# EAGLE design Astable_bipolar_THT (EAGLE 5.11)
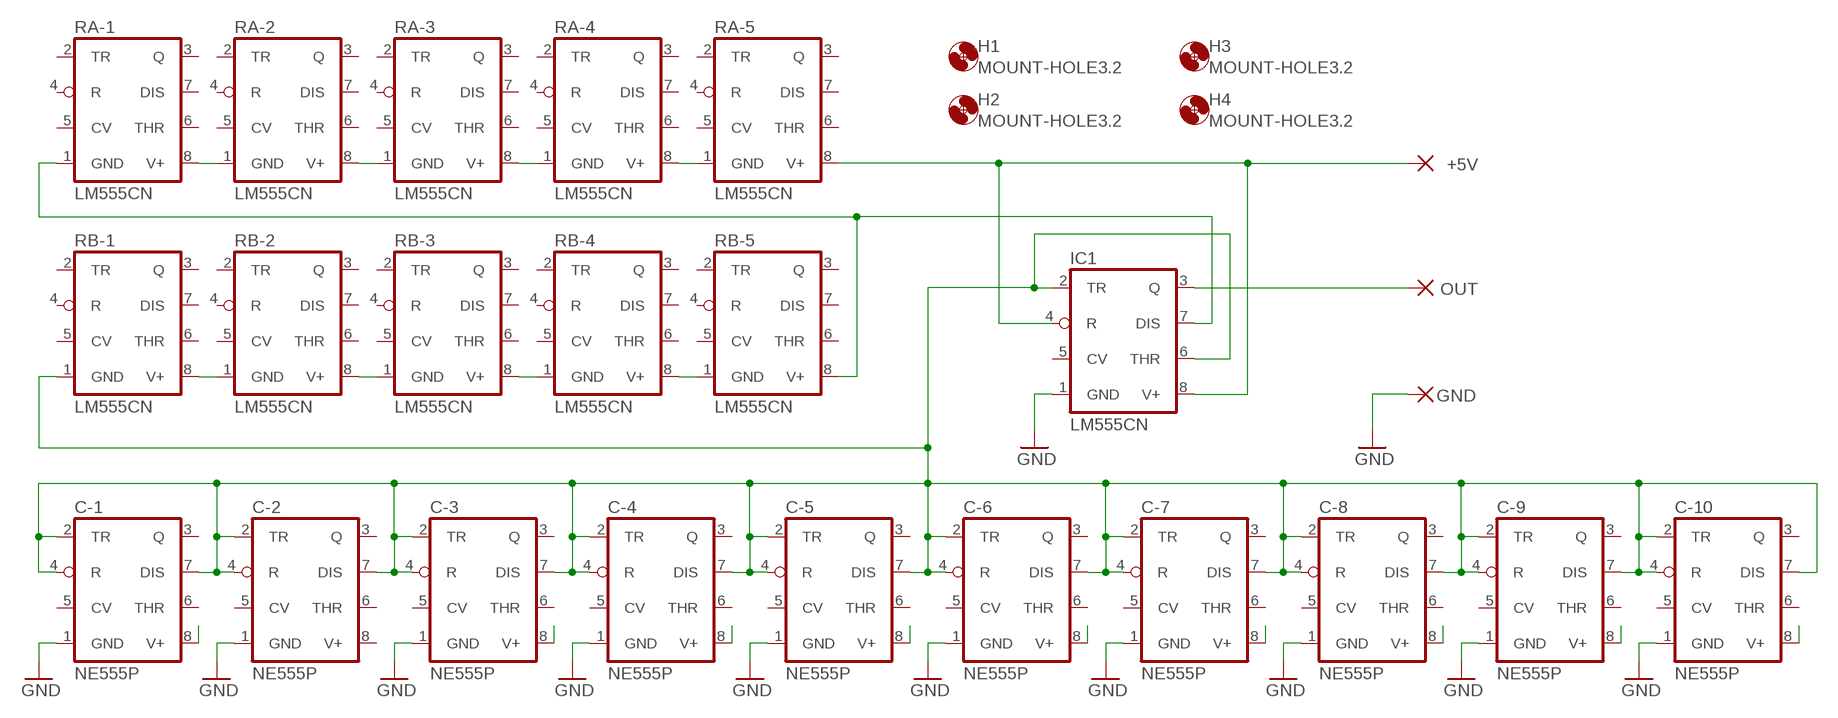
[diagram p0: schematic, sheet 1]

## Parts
+5V  3,17/1,1  [3,17/1,1]
C-1  NE555P  NE555N  [DIL08]
C-2  NE555P  NE555N  [DIL08]
C-3  NE555P  NE555N  [DIL08]
C-4  NE555P  NE555N  [DIL08]
C-5  NE555P  NE555N  [DIL08]
C-6  NE555P  NE555N  [DIL08]
C-7  NE555P  NE555N  [DIL08]
C-8  NE555P  NE555N  [DIL08]
C-9  NE555P  NE555N  [DIL08]
C-10  NE555P  NE555N  [DIL08]
GND  3,17/1,1  [3,17/1,1]
H1  MOUNT-HOLE3.2  [3,2]
H2  MOUNT-HOLE3.2  [3,2]
H3  MOUNT-HOLE3.2  [3,2]
H4  MOUNT-HOLE3.2  [3,2]
IC1  LM555CN  NE555N  [DIL08]
OUT  3,17/1,1  [3,17/1,1]
RA-1  LM555CN  NE555N  [DIL08]
RA-2  LM555CN  NE555N  [DIL08]
RA-3  LM555CN  NE555N  [DIL08]
RA-4  LM555CN  NE555N  [DIL08]
RA-5  LM555CN  NE555N  [DIL08]
RB-1  LM555CN  NE555N  [DIL08]
RB-2  LM555CN  NE555N  [DIL08]
RB-3  LM555CN  NE555N  [DIL08]
RB-4  LM555CN  NE555N  [DIL08]
RB-5  LM555CN  NE555N  [DIL08]

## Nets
GND: C-1.1(GND) C-2.1(GND) C-3.1(GND) C-4.1(GND) C-5.1(GND) C-6.1(GND) C-7.1(GND) C-8.1(GND) C-9.1(GND) C-10.1(GND) GND.1(P) IC1.1(GND)
N$1: +5V.1(P) IC1.4(R) IC1.8(V+) RA-5.8(V+)
N$2: IC1.7(DIS) RA-1.1(GND) RB-5.8(V+)
N$3: C-1.8(V+)
N$4: C-3.8(V+)
N$5: C-4.8(V+)
N$6: C-5.8(V+)
N$7: C-1.2(TR) C-1.4(R) C-1.7(DIS) C-2.2(TR) C-2.4(R) C-2.7(DIS) C-3.2(TR) C-3.4(R) C-3.7(DIS) C-4.2(TR) C-4.4(R) C-4.7(DIS) C-5.2(TR) C-5.4(R) C-5.7(DIS) C-6.2(TR) C-6.4(R) C-6.7(DIS) C-7.2(TR) C-7.4(R) C-7.7(DIS) C-8.2(TR) C-8.4(R) C-8.7(DIS) C-9.2(TR) C-9.4(R) C-9.7(DIS) C-10.2(TR) C-10.4(R) C-10.7(DIS) IC1.2(TR) IC1.6(THR) RB-1.1(GND)
N$8: IC1.3(Q) OUT.1(P)
N$9: RA-1.8(V+) RA-2.1(GND)
N$10: RA-2.8(V+) RA-3.1(GND)
N$11: RA-3.8(V+) RA-4.1(GND)
N$12: RA-4.8(V+) RA-5.1(GND)
N$13: RB-1.8(V+) RB-2.1(GND)
N$14: RB-2.8(V+) RB-3.1(GND)
N$15: RB-3.8(V+) RB-4.1(GND)
N$16: RB-4.8(V+) RB-5.1(GND)
N$17: C-6.8(V+)
N$18: C-7.8(V+)
N$19: C-8.8(V+)
N$20: C-9.8(V+)
N$21: C-10.8(V+)
Unconnected: C-1.3(Q) C-1.5(CV) C-1.6(THR) C-2.3(Q) C-2.5(CV) C-2.6(THR) C-3.3(Q) C-3.5(CV) C-3.6(THR) C-4.3(Q) C-4.5(CV) C-4.6(THR) C-5.3(Q) C-5.5(CV) C-5.6(THR) C-6.3(Q) C-6.5(CV) C-6.6(THR) C-7.3(Q) C-7.5(CV) C-7.6(THR) C-8.3(Q) C-8.5(CV) C-8.6(THR) C-9.3(Q) C-9.5(CV) C-9.6(THR) C-10.3(Q) C-10.5(CV) C-10.6(THR) IC1.5(CV) RA-1.2(TR) RA-1.3(Q) RA-1.4(R) RA-1.5(CV) RA-1.6(THR) RA-1.7(DIS) RA-2.2(TR) RA-2.3(Q) RA-2.4(R) RA-2.5(CV) RA-2.6(THR) RA-2.7(DIS) RA-3.2(TR) RA-3.3(Q) RA-3.4(R) RA-3.5(CV) RA-3.6(THR) RA-3.7(DIS) RA-4.2(TR) RA-4.3(Q) RA-4.4(R) RA-4.5(CV) RA-4.6(THR) RA-4.7(DIS) RA-5.2(TR) RA-5.3(Q) RA-5.4(R) RA-5.5(CV) RA-5.6(THR) RA-5.7(DIS) RB-1.2(TR) RB-1.3(Q) RB-1.4(R) RB-1.5(CV) RB-1.6(THR) RB-1.7(DIS) RB-2.2(TR) RB-2.3(Q) RB-2.4(R) RB-2.5(CV) RB-2.6(THR) RB-2.7(DIS) RB-3.2(TR) RB-3.3(Q) RB-3.4(R) RB-3.5(CV) RB-3.6(THR) RB-3.7(DIS) RB-4.2(TR) RB-4.3(Q) RB-4.4(R) RB-4.5(CV) RB-4.6(THR) RB-4.7(DIS) RB-5.2(TR) RB-5.3(Q) RB-5.4(R) RB-5.5(CV) RB-5.6(THR) RB-5.7(DIS)

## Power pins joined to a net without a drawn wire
V+: C-2.8(V+)

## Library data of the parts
+5V GND OUT = wirepad:3,17/1,1: THROUGH-HOLE PAD
C-1-C-10 IC1 RA-1-RA-5 RB-1-RB-5 = linear:*555: TIMER
H1-H4 = holes:MOUNT-HOLE: MOUNTING HOLE with drill center marker

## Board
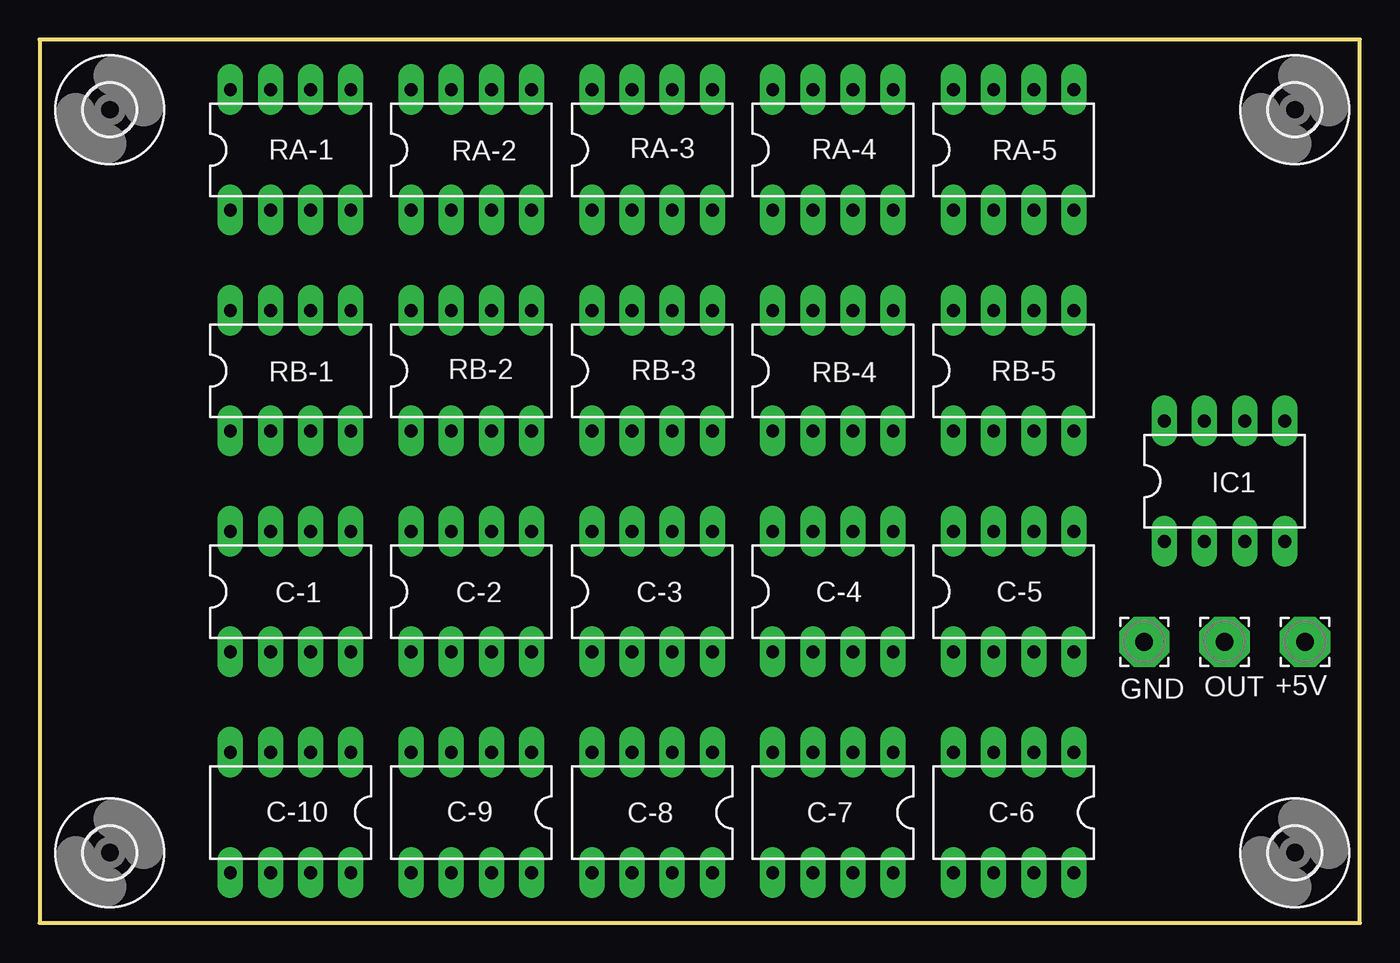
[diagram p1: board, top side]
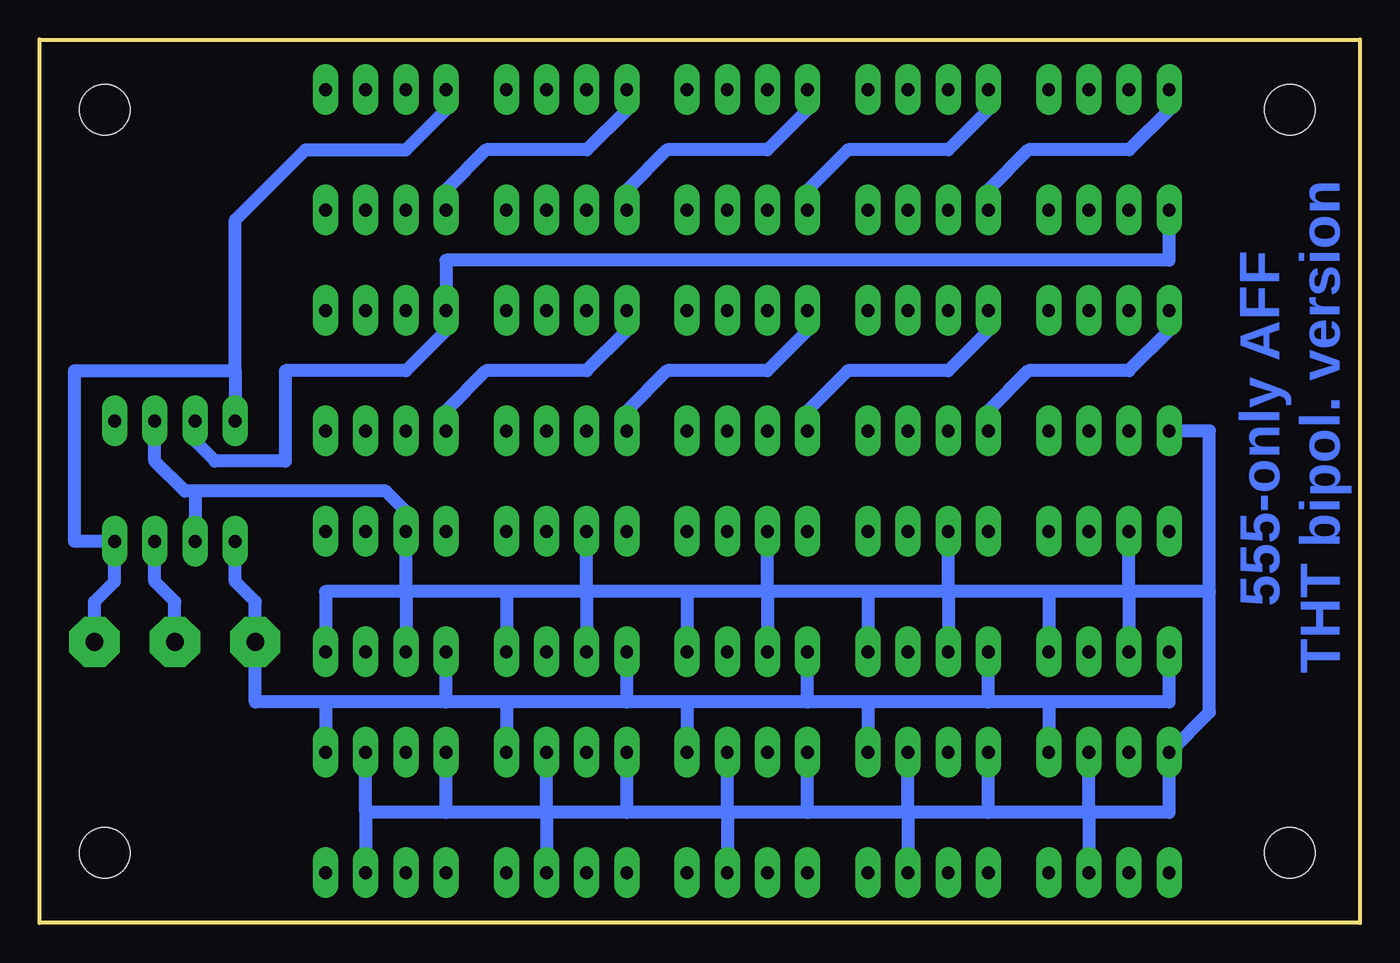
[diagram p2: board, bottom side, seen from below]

Size 83.49 x 55.87 mm. Coordinates in mm from the lower left corner, seen from the top.
Outline: 0,0 83.49,0 83.49,55.87 0,55.87 0,0
Copper layers 16: Bottom 0.035mm
Design rules "default *": minimum track width 0.4mm, minimum drill 0.8mm, track to track 0.4mm, track to pad 0.4mm, pad to pad 0.4mm, via to via 0.4mm, smd to smd 0.4mm, copper to edge 1mm, drill to drill 0.8mm, minimum pad ring 0.4mm, minimum via ring 8mil, stop-mask expansion 4mil, vias tented up to drill 0mil, thermal gap 10mil

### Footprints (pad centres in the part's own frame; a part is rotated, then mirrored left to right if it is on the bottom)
3,17/1,1 = drill 1.118 pad 3.175 octagon: 1 0,0
DIL08 = drill 0.813 long: 1 -3.81,-3.81; 2 -1.27,-3.81; 3 1.27,-3.81; 4 3.81,-3.81; 5 3.81,3.81; 6 1.27,3.81; 7 -1.27,3.81; 8 -3.81,3.81
3,2 = hole 3.2: 0,0

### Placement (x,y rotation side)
+5V  80.01,17.78 0 top
C-1  15.88,20.95 0 top
C-2  27.3,20.95 0 top
C-3  38.73,20.95 0 top
C-4  50.16,20.95 0 top
C-5  61.59,20.95 0 top
C-6  61.59,6.99 180 top
C-7  50.16,6.99 180 top
C-8  38.73,6.99 180 top
C-9  27.3,6.99 180 top
C-10  15.88,6.99 180 top
GND  69.85,17.78 0 top
H1  79.38,4.45 0 top
H2  79.38,51.44 0 top
H3  4.45,4.45 0 top
H4  4.45,51.44 0 top
IC1  74.93,27.94 0 top
OUT  74.93,17.78 0 top
RA-1  15.88,48.9 0 top
RA-2  27.3,48.9 0 top
RA-3  38.73,48.9 0 top
RA-4  50.16,48.9 0 top
RA-5  61.59,48.9 0 top
RB-1  15.88,34.92 0 top
RB-2  27.3,34.92 0 top
RB-3  38.73,34.92 0 top
RB-4  50.16,34.92 0 top
RB-5  61.59,34.92 0 top

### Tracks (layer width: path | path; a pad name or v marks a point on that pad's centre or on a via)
GND
  Bottom 0.813: C-1.1 12.06,13.97 19.68,13.97 | 19.68,13.97 23.5,13.97 | 23.5,13.97 31.11,13.97 | 31.11,13.97 34.92,13.97 | 34.92,13.97 42.55,13.97 | 42.55,13.97 46.35,13.97 | 46.35,13.97 53.98,13.97 | 53.98,13.97 57.78,13.97 | 57.78,13.97 65.41,13.97 | 65.41,13.97 69.85,13.97 GND.1 69.85,20.32 71.12,21.59 IC1.1 | 23.5,13.97 C-2.1 | 19.68,13.97 C-10.1 | 31.11,13.97 C-9.1 | 34.92,13.97 C-3.1 | 42.55,13.97 C-8.1 | 46.35,13.97 C-4.1 | 53.98,13.97 C-7.1 | 57.78,13.97 C-5.1 | 65.41,13.97 C-6.1
N$1
  Bottom 0.813: 71.12,34.92 81.28,34.92 81.28,24.13 IC1.4 78.74,21.59 80.01,20.32 +5V.1 | 71.12,34.92 IC1.8 | RA-5.8 57.78,51.44 60.33,48.9 66.67,48.9 71.12,44.45 71.12,34.92
N$2
  Bottom 0.813: RA-1.1 12.06,41.91 57.78,41.91 RB-5.8 57.78,37.47 60.33,34.92 67.94,34.92 67.94,29.21 72.39,29.21 73.66,30.48 IC1.7
N$7
  Bottom 0.813: 26.04,20.95 31.11,20.95 | 31.11,20.95 37.47,20.95 | 37.47,20.95 42.55,20.95 | 42.55,20.95 48.9,20.95 | 48.9,20.95 53.98,20.95 | 53.98,20.95 60.33,20.95 | 17.14,6.99 23.5,6.99 | 23.5,6.99 28.57,6.99 | 28.57,6.99 34.92,6.99 | 34.92,6.99 40.01,6.99 | 40.01,6.99 46.35,6.99 | 46.35,6.99 51.44,6.99 | 9.53,20.95 14.61,20.95 | 14.61,20.95 19.68,20.95 | 19.68,20.95 26.04,20.95 | RB-1.1 9.53,31.11 9.53,20.95 | IC1.6 76.2,29.21 74.3,27.3 73.66,27.3 | 73.66,27.3 IC1.2 | 14.61,20.95 C-1.2 | 26.04,20.95 C-2.2 | 37.47,20.95 C-3.2 | 48.9,20.95 C-4.2 | 60.33,20.95 C-5.2 | 51.44,6.99 57.78,6.99 | 57.78,6.99 62.87,6.99 | 62.87,6.99 C-6.2 | 51.44,6.99 C-7.2 | 40.01,6.99 C-8.2 | 28.57,6.99 C-9.2 | 17.14,6.99 C-10.2 | 14.61,20.95 C-1.7 | 26.04,20.95 C-2.7 | 37.47,20.95 C-3.7 | 48.9,20.95 C-4.7 | 60.33,20.95 C-5.7 60.33,26.04 61.59,27.3 73.66,27.3 | 60.33,20.95 65.41,20.95 C-5.4 | 57.78,6.99 C-6.4 | 62.87,6.99 C-6.7 | 51.44,6.99 C-7.7 | 46.35,6.99 C-7.4 | 53.98,20.95 C-4.4 | 42.55,20.95 C-3.4 | 31.11,20.95 C-2.4 | 19.68,20.95 C-1.4 | 17.14,6.99 C-10.7 | 28.57,6.99 C-9.7 | 40.01,6.99 C-8.7 | 34.92,6.99 C-8.4 | 23.5,6.99 C-9.4 | 17.14,6.99 12.06,6.99 C-10.4 9.53,13.34 9.53,20.95
N$8
  Bottom 0.813: IC1.3 76.2,21.59 74.93,20.32 OUT.1
N$9
  Bottom 0.813: RA-1.8 12.06,51.44 14.61,48.9 20.95,48.9 23.5,46.35 RA-2.1
N$10
  Bottom 0.813: RA-2.8 23.5,51.44 26.04,48.9 32.38,48.9 34.92,46.35 RA-3.1
N$11
  Bottom 0.813: RA-3.8 34.92,51.44 37.47,48.9 43.81,48.9 46.35,46.35 RA-4.1
N$12
  Bottom 0.813: RA-4.8 46.35,51.44 48.9,48.9 55.24,48.9 57.78,46.35 RA-5.1
N$13
  Bottom 0.813: RB-1.8 12.06,37.47 14.61,34.92 20.95,34.92 23.5,32.38 RB-2.1
N$14
  Bottom 0.813: RB-2.8 23.5,37.47 26.04,34.92 32.38,34.92 34.92,32.38 RB-3.1
N$15
  Bottom 0.813: RB-3.8 34.92,37.47 37.47,34.92 43.81,34.92 46.35,32.38 RB-4.1
N$16
  Bottom 0.813: RB-4.8 46.35,37.47 48.9,34.92 55.24,34.92 57.78,32.38 RB-5.1

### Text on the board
Bottom: THT bipol. version | 555-only AFF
